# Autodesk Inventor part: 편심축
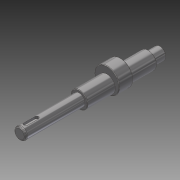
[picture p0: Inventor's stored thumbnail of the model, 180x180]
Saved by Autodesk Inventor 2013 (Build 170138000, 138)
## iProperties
Created: 2016-02
Part Number: 편심축
Material: 강철, 연강
Document SubType Name: Modeling
Designer: mduedu
Density: 1 g/cm^3
Author: mduedu
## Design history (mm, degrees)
sketch "스케치1"
  geometry: C1 r 6 at (0, 0); 1 further point
  constraints: 1 centre point, 1 coincident
  dimensions: "d0" = 12 diameter of C1
extrude "돌출1" new body sketch "스케치1" distance "d1" = 142; taper "d2" = 0 deg
chamfer "모따기1" distance "d3" = 0.5; stored, may be unused: second distance "d4" = 2, angle "d5" = 45 deg
node "작업 평면2"
sketch "스케치3"
  geometry: C1 r 8.5 at (0, 0); 1 further point
  constraints: 1 centre point, 1 coincident
  dimensions: "d12" = 17 diameter of C1
extrude "돌출3" join sketch "스케치3" distance "d13" = 70; taper "d14" = 0 deg
node "작업 평면3"
sketch "스케치4"
  geometry: L1 (0, 142)-(0, 0); L2 (-2, 136)-(-2, 125); L3 (2, 125)-(2, 136); L4 (6, 142)-(-6, 142) reference; A1 r 2 centre (0, 136) between (2, 136) and (-2, 136); A2 r 2 centre (0, 125) between (-2, 125) and (2, 125)
  constraints: 6 end point, 4 point on circle, 4 tangent, 2 centre point, 2 point on line, 1 midpoint, 1 parallel
  dimensions: "d15" = 4 distance between parallel lines of L2 L3; "d18" = 15 dimension on A2 A1; "d36" = 4 distance edge to line of A1 L4
extrude "돌출4" cut sketch "스케치4" distance "d19" = 2.5; taper "d20" = 0 deg
node "작업 평면1"
sketch "스케치2"
  geometry: C1 r 12.5 at (0, 3); C2 r 8.5 at (0, 0) reference; 1 further point
  constraints: 1 centre point, 1 vertical alignment
  dimensions: "d7" = 25 diameter of C1; "d32" = 3 distance of C1.centre point (0, 0)
extrude "돌출2" join sketch "스케치2" stored distance "d8" = 14; taper "d9" = 0 deg
sketch "스케치5"
  geometry: L1 (6, 82)-(6, 142) reference; L2 (-6, 82)-(-6, 142) reference; L3 (6, 115)-(-6, 115); L4 (6, 116.5)-(4.5, 115); L5 (6, 116.5)-(6, 115); L6 (4.5, 115)-(6, 115); L7 (6, 142)-(-6, 142) reference; 1 further point
  constraints: 8 end point, 4 point on line, 2 collinear, 1 perpendicular
  dimensions: "d22" = 3 diameter of L4.start L3; "d24" = 45 deg angle of L3 L4; "d37" = 27 distance between parallel lines of L7 L3
revolve "회전1" sketch "스케치5" stored, may be unused: angle "d25" = 90 deg
sketch "스케치6"
  geometry: L1 (6, 116.5)-(4.5, 115) reference; L2 (6, 113.5)-(4.5, 115) reference; 2 further points
  constraints: 1 coincident
node "작업 평면4"
chamfer "모따기2" distance "d33" = 0.5; stored, may be unused: second distance "d34" = 2, angle "d35" = 45 deg
sketch "스케치8"
  geometry: L1 (5.1, 142)-(6, 140.441); L2 (6, 82)-(6, 142) reference; L3 (6, 142)-(-6, 142) reference; L4 (0, 142)-(0, 86.696); 1 further point
  constraints: 4 end point, 2 point on line, 1 midpoint, 1 perpendicular
  dimensions: "d38" = 10.2 diameter of L1.start L4; "d43" = 30 deg angle of L2 L1
revolve "회전2" sketch "스케치8" stored, may be unused: angle "d45" = 90 deg
fillet "모깎기1" dims "d46" = 2, "d47" = 1
node "솔리드1"
other parameters: "d6" = -47, "d11" = -12, "d26" = 28
